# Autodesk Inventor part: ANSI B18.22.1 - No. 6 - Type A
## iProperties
Comments: To add or edit properties for Autodesk Inventor files, use iProperties.
Created: 2005-06
Part Number: ANSI B18.22.1 - No. 6 - Type A
Vendor: Autodesk Inc.
Document SubType Name: Modeling
Designer: John Blackburn
Material: Default
Description: Washer A
Standard: ANSI B18.22.1
Alert: To add or edit properties for Autodesk Inventor files, use iProperties.
Control State: 0
Master: False
Checked Out: False
Shininess: 64.0
Length Units: 11272
Angle Units: 11279
Time Units: 11290
Mass Units: 11286
Length Display Precision: 3
Angle Display Precision: 2
Compacted: True
Classification: un/spsc 31161807
Density: 0.0
Volumn: 0.0
Area: 0.0
PropertySet Name: Model Information
Author: John Blackburn
Revision Number: 8
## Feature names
1. Body [Extrusion]
